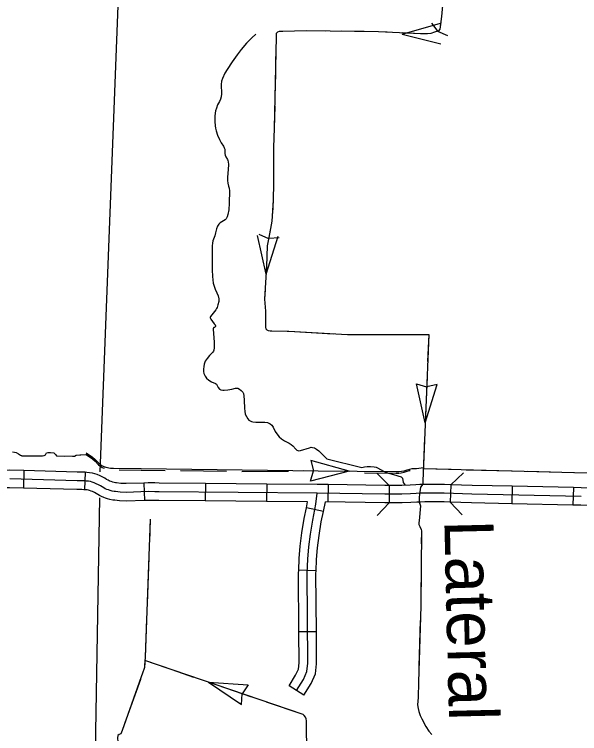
# Model space of a CAD drawing. Extents: x 1196286 to 1268366, y 2040822 to 2082115.
# Drawn here: x 1219934 to 1221760, y 2061099 to 2063420 of the extents above; entities that cross this region are included whole.
import ezdxf

# ---------------------------------------------------------------- set-up
doc = ezdxf.new("R2010")
doc.units = 0
for name, color, linetype in [('60', 7, 'Continuous'), ('61', 7, 'Continuous'), ('62', 7, 'Continuous'), ('63', 7, 'Continuous'), ('Level 83', 7, 'Continuous')]:
    doc.layers.add(name, color=color, linetype=linetype)

msp = doc.modelspace()

# ---------------------------------------------------------------- linework, layer by layer
at = {"layer": '60'}
for points in [[(1220211.7, 2061943.6), (1220286.5, 2063894.5)], [(1220209.5, 2061859.4), (1220176.2, 2059909.8)]]:
    msp.add_lwpolyline(points, dxfattribs=at)
at = {"layer": '61'}
for p, q in [((1219965.2, 2061947.6), (1219963.7, 2061891.3)), ((1220163.5, 2061942.2), (1220161.1, 2061886)), ((1220352.4, 2061907.5), (1220354.2, 2061851.3)), ((1220551.5, 2061905.9), (1220551, 2061849.7)), ((1220749.4, 2061904.4), (1220749, 2061848.2)), ((1220947.7, 2061902.6), (1220946.7, 2061846.3)), ((1221145.1, 2061899.5), (1221145.3, 2061843.3)), ((1221344, 2061902), (1221342.2, 2061845.8)), ((1221541.6, 2061897.1), (1221540.5, 2061840.9)), ((1221739.6, 2061893), (1221738.4, 2061836.7)), ((1220932.4, 2061816), (1220877.3, 2061827.3)), ((1220908.8, 2061624.2), (1220852.6, 2061626.7)), ((1220909.7, 2061427.7), (1220853.5, 2061427.3)), ((1220869.3, 2061223.5), (1220821.7, 2061253.5))]:
    msp.add_line(p, q, dxfattribs=at)
for points in [[(1219965.2, 2061947.6), (1219919.7, 2061948.8), (1219766.3, 2061948)], [(1220163.5, 2061942.2), (1220160.9, 2061942.3), (1220154.6, 2061942.6), (1220137.6, 2061942.9), (1219965.2, 2061947.6)], [(1221764.9, 2061864.3), (1221411.8, 2061871.7), (1221322.6, 2061874.6), (1221286.6, 2061874.9), (1221259.2, 2061874.8), (1221245.3, 2061874.4), (1221232.4, 2061873.7), (1221213.9, 2061872.9), (1221186.2, 2061871.7), (1221157.7, 2061871.5), (1221130.9, 2061871.3), (1220912, 2061875.1), (1220401.6, 2061879), (1220387.6, 2061879.6), (1220366.5, 2061879.8), (1220295.3, 2061877.5), (1220276.4, 2061878.2), (1220261.3, 2061879.8), (1220256.4, 2061880.2), (1220250, 2061881.6), (1220243.8, 2061883.5), (1220238.2, 2061885.4), (1220233.1, 2061887.2), (1220228, 2061889.3), (1220223.1, 2061892), (1220218, 2061894.9), (1220212.5, 2061898.1), (1220206.1, 2061901.4), (1220199, 2061905.5), (1220192, 2061908.2), (1220185.7, 2061910.4), (1220180.1, 2061912), (1220173.3, 2061913.1), (1220166.1, 2061913.9), (1220159.6, 2061914.2), (1220153.6, 2061914.5), (1220136.9, 2061914.8), (1219919.4, 2061920.7)], [(1220352.4, 2061907.5), (1220295.4, 2061905.6), (1220278.3, 2061906.3), (1220264.1, 2061907.7), (1220260.7, 2061908.1), (1220257, 2061908.9), (1220252.4, 2061910.3), (1220247.3, 2061912), (1220243.1, 2061913.4), (1220240.2, 2061914.7), (1220236.9, 2061916.5), (1220232.2, 2061919.2), (1220226, 2061922.8), (1220219.6, 2061926.1), (1220211.3, 2061930.8), (1220201.7, 2061934.7), (1220194, 2061937.2), (1220186.2, 2061939.4), (1220177.3, 2061940.9), (1220168.3, 2061942), (1220163.5, 2061942.2)], [(1220551.5, 2061905.9), (1220402.3, 2061907.1), (1220388.4, 2061907.7), (1220366.2, 2061907.9), (1220352.4, 2061907.5)], [(1220749.4, 2061904.4), (1220551.5, 2061905.9)], [(1220947.7, 2061902.6), (1220912.4, 2061903.2), (1220749.4, 2061904.4)], [(1221145.1, 2061899.5), (1221131.1, 2061899.4), (1220947.7, 2061902.6)], [(1221344, 2061902), (1221323.2, 2061902.7), (1221286.7, 2061903), (1221258.8, 2061902.9), (1221244.1, 2061902.5), (1221231, 2061901.8), (1221212.7, 2061901), (1221185.5, 2061899.8), (1221157.5, 2061899.6), (1221145.1, 2061899.5)], [(1221541.6, 2061897.1), (1221412.5, 2061899.8), (1221344, 2061902)], [(1219963.7, 2061891.3), (1219919.1, 2061892.5), (1219766.6, 2061891.7)], [(1220161.1, 2061886), (1220158.3, 2061886.1), (1220152.7, 2061886.4), (1220136.2, 2061886.7), (1219963.7, 2061891.3)], [(1220354.2, 2061851.3), (1220295.2, 2061849.4), (1220274.4, 2061850.1), (1220258.4, 2061851.8), (1220252.1, 2061852.4), (1220242.9, 2061854.3), (1220235.2, 2061856.7), (1220229.1, 2061858.7), (1220223, 2061860.9), (1220215.8, 2061863.9), (1220209.3, 2061867.5), (1220203.9, 2061870.6), (1220199, 2061873.4), (1220192.7, 2061876.6), (1220186.7, 2061880.1), (1220182.3, 2061881.8), (1220177.4, 2061883.5), (1220173.9, 2061884.5), (1220169.4, 2061885.2), (1220163.8, 2061885.9), (1220161.1, 2061886)], [(1220845.5, 2061238.5), (1220867.7, 2061273.8), (1220879.1, 2061299.3), (1220882.3, 2061325.9), (1220880.3, 2061616.7), (1220882.2, 2061662.2), (1220885, 2061701.4), (1220890.9, 2061742.5), (1220898, 2061787.7), (1220908.4, 2061839), (1220912, 2061875.1)], [(1221739.6, 2061893), (1221541.6, 2061897.1)], [(1221937.5, 2061889.1), (1221765.4, 2061892.4), (1221739.6, 2061893)], [(1220551, 2061849.7), (1220400.9, 2061850.8), (1220386.9, 2061851.4), (1220366.8, 2061851.7), (1220354.2, 2061851.3)], [(1220749, 2061848.2), (1220551, 2061849.7)], [(1220881.4, 2061847.2), (1220749, 2061848.2)], [(1220877.3, 2061827.3), (1220881.4, 2061847.2)], [(1220932.4, 2061816), (1220938.7, 2061846.5)], [(1221145.3, 2061843.3), (1221130.7, 2061843.2), (1220938.7, 2061846.5)], [(1221342.2, 2061845.8), (1221322.1, 2061846.5), (1221286.6, 2061846.7), (1221259.6, 2061846.6), (1221246.4, 2061846.3), (1221233.7, 2061845.6), (1221215.1, 2061844.8), (1221186.9, 2061843.6), (1221157.9, 2061843.3), (1221145.3, 2061843.3)], [(1221540.5, 2061840.9), (1221411, 2061843.6), (1221342.2, 2061845.8)], [(1221738.4, 2061836.7), (1221540.5, 2061840.9)], [(1221936.4, 2061832.8), (1221764.3, 2061836.2), (1221738.4, 2061836.7)], [(1220852.6, 2061626.7), (1220854.2, 2061663.7), (1220857, 2061704.3), (1220863, 2061746.7), (1220870.3, 2061792.7), (1220877.3, 2061827.3)], [(1220908.8, 2061624.2), (1220910.3, 2061660.6), (1220912.9, 2061698.4), (1220918.7, 2061738.3), (1220925.6, 2061782.7), (1220932.4, 2061816)], [(1220853.5, 2061427.3), (1220852.2, 2061617.2), (1220852.6, 2061626.7)], [(1220909.7, 2061427.7), (1220908.4, 2061616.2), (1220908.8, 2061624.2)], [(1220821.7, 2061253.5), (1220842.8, 2061287.1), (1220851.7, 2061306.9), (1220854.2, 2061327.5), (1220853.5, 2061427.3)], [(1220869.3, 2061223.5), (1220892.5, 2061260.5), (1220906.5, 2061291.7), (1220910.5, 2061324.3), (1220909.7, 2061427.7)]]:
    msp.add_lwpolyline(points, dxfattribs=at)
at = {"layer": '62'}
for points in [[(1220714.2, 2063355.6), (1220701.3, 2063344.2), (1220683.9, 2063326.8), (1220666.9, 2063306.9), (1220653.5, 2063289.3), (1220637.3, 2063266.3), (1220621.4, 2063241.7), (1220614.4, 2063229.8), (1220606.5, 2063213.4), (1220603.4, 2063204), (1220602.2, 2063193.4), (1220603.4, 2063163.5), (1220601.8, 2063153.5), (1220599.7, 2063146), (1220596.4, 2063139), (1220590.3, 2063127.7), (1220586.7, 2063117.4), (1220583.9, 2063108.2), (1220581.7, 2063092.3), (1220581.4, 2063073.7), (1220582.4, 2063060), (1220583.7, 2063052.3), (1220586, 2063043.6), (1220590.8, 2063030.6), (1220596.9, 2063016.1), (1220602.7, 2063005.5), (1220609.3, 2062995), (1220612.3, 2062989.3), (1220613.8, 2062985.4), (1220614.2, 2062980.6), (1220614.1, 2062971.1), (1220614.7, 2062965.9), (1220617.2, 2062960.4), (1220622.7, 2062951.9), (1220624, 2062948.4), (1220624.9, 2062944.3), (1220625.5, 2062935.5), (1220624.8, 2062919.3), (1220622.3, 2062894.9), (1220622.6, 2062884.3), (1220623.9, 2062875.7), (1220626.2, 2062865.5), (1220627.7, 2062859), (1220628.8, 2062850.5), (1220628.5, 2062810.8), (1220627.1, 2062789.2), (1220624, 2062773.7), (1220621.7, 2062766.8), (1220618.3, 2062760.5), (1220614.9, 2062757.4), (1220599.1, 2062747.1), (1220594.8, 2062742.8), (1220590.2, 2062736.2), (1220587.3, 2062728.1), (1220584.1, 2062714.8), (1220581.4, 2062705.3), (1220575.7, 2062689.5), (1220574.2, 2062681.3), (1220573.6, 2062672.9), (1220573.1, 2062639.6), (1220572.8, 2062595.9), (1220573.8, 2062574.3), (1220575, 2062563), (1220576.9, 2062553), (1220579.4, 2062543.2), (1220583.1, 2062533.1), (1220588.7, 2062521.7), (1220592.6, 2062511.2), (1220594.2, 2062502.3), (1220594.3, 2062493.5), (1220591.9, 2062482.3), (1220589, 2062473.6), (1220587.6, 2062470.3), (1220585.3, 2062466.9), (1220568.2, 2062445.1), (1220567.1, 2062442.7), (1220567, 2062440.2), (1220567.4, 2062438.3), (1220568.4, 2062436.8), (1220579.6, 2062421.7), (1220582.6, 2062418.4), (1220583.3, 2062417.4), (1220584, 2062416.1), (1220584.4, 2062414.8), (1220584.4, 2062413.7), (1220584.1, 2062412.5), (1220583.3, 2062411.3), (1220581.6, 2062410), (1220578.6, 2062409), (1220577.8, 2062408.2), (1220577.2, 2062407.6), (1220576.6, 2062405.9), (1220576.4, 2062404.1)], [(1220576.4, 2062404.1), (1220579.1, 2062361.7), (1220579.3, 2062343.6), (1220578.7, 2062336.8), (1220577.1, 2062332.6), (1220574.2, 2062328.6), (1220565, 2062319.1), (1220556.6, 2062309.5), (1220550.4, 2062300.4), (1220547.3, 2062291.4), (1220545.8, 2062283.8), (1220544.9, 2062275.3), (1220545.1, 2062267.9), (1220546.5, 2062261.1), (1220550.1, 2062252.4), (1220555, 2062246.1), (1220562, 2062239.4), (1220571.5, 2062234.5), (1220584.3, 2062228.9), (1220587, 2062226.8), (1220589.7, 2062222.8), (1220592.9, 2062215.9), (1220596.7, 2062210.6), (1220601.6, 2062208.3), (1220607.4, 2062207.2), (1220612.4, 2062207.1), (1220623.7, 2062208.2), (1220636.4, 2062210.6), (1220648.4, 2062213.5), (1220652.3, 2062213.8), (1220655.8, 2062213.2), (1220661.4, 2062210.7), (1220666.9, 2062206.4), (1220671.8, 2062201.1), (1220674.2, 2062196.1), (1220675.8, 2062189), (1220676.9, 2062175.3), (1220677.5, 2062147.6), (1220678.4, 2062139.3), (1220679.9, 2062129.8), (1220683.7, 2062122.2), (1220688.5, 2062114.6), (1220692, 2062110.9), (1220695.8, 2062108.3), (1220700.7, 2062106.4), (1220704.8, 2062105.1), (1220714.7, 2062104.4), (1220743.6, 2062104.5), (1220752.2, 2062102.7), (1220756.4, 2062100.9), (1220760.6, 2062099), (1220765.8, 2062093.9), (1220769.8, 2062087.8), (1220776.8, 2062074.4), (1220782.5, 2062066.2), (1220789.4, 2062056.8), (1220796.6, 2062050.2), (1220807.2, 2062043.3), (1220822.3, 2062035.8), (1220827.8, 2062032.3), (1220833.8, 2062027.4), (1220843.3, 2062016.9), (1220846.1, 2062014), (1220849.4, 2062012.5), (1220852.3, 2062012), (1220858, 2062012.4), (1220887, 2062021.4), (1220893.1, 2062022.8), (1220897.6, 2062022.6), (1220903.3, 2062021.5), (1220909.9, 2062017), (1220917.2, 2062011), (1220925.9, 2062002.7), (1220943.9, 2061986.2), (1221056.1, 2061958.1), (1221064.7, 2061960), (1221074.2, 2061960.9), (1221084.9, 2061961.1), (1221096.7, 2061960.1), (1221102.5, 2061958.5), (1221107.4, 2061956.4), (1221126.8, 2061946.3), (1221134.3, 2061942.9), (1221142.4, 2061939.9), (1221159.2, 2061934.6), (1221183.9, 2061927.9), (1221187.7, 2061923.2), (1221190.5, 2061908.9), (1221196.1, 2061900.3)]]:
    msp.add_lwpolyline(points, dxfattribs=at)
at = {"layer": '63'}
for p, q in [((1221187.2, 2063356.5), (1221311.1, 2063391.4)), ((1221281.3, 2063392), (1221302, 2063364.6)), ((1221333.8, 2063351), (1221302.3, 2063364.4)), ((1221187.2, 2063356.5), (1221311.9, 2063324.8)), ((1220724.3, 2062710.9), (1220755.3, 2062696.2)), ((1220747.4, 2062581.2), (1220719.4, 2062706.8)), ((1220747.4, 2062581.2), (1220786, 2062704)), ((1220789.9, 2062699), (1220755.7, 2062696.2)), ((1221261.2, 2062102.3), (1221232.9, 2062227.9)), ((1221232.9, 2062227.9), (1221265.6, 2062217.7)), ((1221261.2, 2062102.3), (1221299.4, 2062225.2)), ((1221299.4, 2062225.2), (1221266, 2062217.7)), ((1221015.7, 2061946.1), (1220891.6, 2061980.4)), ((1220891.6, 2061980.4), (1220900.2, 2061947.3)), ((1220891.1, 2061913.8), (1220900.2, 2061946.8)), ((1221015.7, 2061946.1), (1220891.1, 2061913.8)), ((1220561.2, 2061264.6), (1220668, 2061192.9)), ((1220561.2, 2061264.6), (1220689.6, 2061255.9)), ((1220689.6, 2061255.9), (1220670.5, 2061227.5)), ((1220668, 2061192.9), (1220670.3, 2061227.1))]:
    msp.add_line(p, q, dxfattribs=at)
for points in [[(1221323.6, 2063520.7), (1221314.1, 2063413.2), (1221308.1, 2063372.2), (1221303.7, 2063366.5), (1221291, 2063362), (1221279.5, 2063357.9), (1221269.1, 2063357.5), (1221246.5, 2063357.3), (1221110.3, 2063363.9), (1220876.8, 2063366.4), (1220801.6, 2063364.7), (1220790, 2063364.1), (1220784, 2063362.6), (1220780.2, 2063357.8), (1220779.8, 2063347.8), (1220773.6, 2063052.9), (1220770.9, 2062989.9), (1220771.7, 2062875.6), (1220770.5, 2062819.9), (1220765.8, 2062753), (1220756.1, 2062699.4), (1220751.3, 2062672.9), (1220748.5, 2062606.3), (1220744.2, 2062536.1), (1220742.7, 2062501), (1220745.9, 2062462), (1220745.2, 2062415.9), (1220745.5, 2062410.8), (1220747, 2062405.5), (1220749.4, 2062401.8), (1220753.9, 2062399.4), (1220760.3, 2062398.4), (1220820.8, 2062397.5), (1221010.7, 2062386.4), (1221272.6, 2062387.3), (1221253.6, 2061913.7), (1221253.4, 2061903.5), (1221249.9, 2061899.3), (1221246.4, 2061894.3), (1221245.2, 2061887), (1221242.7, 2061872.4), (1221241.7, 2061859.5), (1221241.3, 2061849.8), (1221241.2, 2061848), (1221243.7, 2061840.9), (1221245.7, 2061833.9), (1221241.3, 2061785.6), (1221241.1, 2061779.7), (1221240.8, 2061773.7), (1221244.2, 2061767.1), (1221248.4, 2061758.1), (1221248.7, 2061753), (1221246.6, 2061510.8), (1221239.3, 2061264.7), (1221238.1, 2061215.8), (1221237.2, 2061203.8), (1221236.6, 2061191.9), (1221238, 2061179.8), (1221240.8, 2061170), (1221244.9, 2061157.8), (1221250.4, 2061147), (1221256.3, 2061134.7), (1221262.7, 2061122.4), (1221272.7, 2061106.8), (1221282.3, 2061095.7)], [(1221311.5, 2063395.2), (1221308.1, 2063372.2), (1221303.7, 2063366.5), (1221291, 2063362), (1221279.5, 2063357.9), (1221269.1, 2063357.5), (1221246.5, 2063357.3), (1221187.3, 2063360.2)], [(1220939.9, 2063365.7), (1220876.8, 2063366.4), (1220801.6, 2063364.7), (1220791.4, 2063364.2)], [(1221063.6, 2063364.4), (1220989.4, 2063365.2)], [(1221137.8, 2063362.6), (1221110.3, 2063363.9), (1221063.6, 2063364.4)], [(1220779.2, 2063322), (1220776.2, 2063173.6)], [(1220775.1, 2063124.1), (1220773.6, 2063052.9), (1220770.9, 2062989.9), (1220771, 2062975.6)], [(1220771.3, 2062926.1), (1220771.7, 2062875.6), (1220770.5, 2062819.9), (1220767.6, 2062777.8)], [(1220761.4, 2062728.7), (1220756.1, 2062699.4), (1220751.3, 2062672.9), (1220748.5, 2062606.3), (1220747, 2062581.2)], [(1220744.1, 2062531.8), (1220742.7, 2062501), (1220745.9, 2062462), (1220745.8, 2062457.7)], [(1220745.8, 2062457.7), (1220745.2, 2062415.9), (1220745.5, 2062410.8), (1220747, 2062405.5), (1220749.4, 2062401.8), (1220753.9, 2062399.4), (1220760.3, 2062398.4), (1220766.1, 2062398.4)], [(1220815.6, 2062397.6), (1220820.8, 2062397.5), (1220963.9, 2062389.1)], [(1221013.3, 2062386.4), (1221161.8, 2062386.9)], [(1221211.3, 2062387.1), (1221272.6, 2062387.3), (1221269.1, 2062300.2)], [(1221267.1, 2062250.7), (1221261.2, 2062102.3)], [(1221259.2, 2062052.9), (1221253.6, 2061913.7), (1221253.4, 2061904.5)], [(1219928.1, 2062007.8), (1219934.7, 2062007.5), (1219940.4, 2062005.9), (1219947.4, 2062001.7), (1219954.3, 2061997.2), (1219958.7, 2061995.6), (1219963.3, 2061994.9), (1220024.7, 2061995.1), (1220030.5, 2061996.3), (1220034.4, 2061998.5), (1220038.1, 2062005.2), (1220042.3, 2062005.8), (1220051.3, 2062006), (1220062.3, 2062004.5), (1220066.9, 2061999.8), (1220070.2, 2061995.2), (1220122.3, 2061993.8), (1220128.3, 2061994.8), (1220133.4, 2061997.1), (1220165.5, 2062000.1)], [(1219957.3, 2061996.1), (1219958.7, 2061995.6), (1219963.3, 2061994.9), (1220024.7, 2061995.1), (1220030.5, 2061996.3), (1220034.4, 2061998.5), (1220038.1, 2062005.2), (1220042.3, 2062005.8), (1220051.3, 2062006), (1220062.3, 2062004.5), (1220066.9, 2061999.8), (1220070.2, 2061995.2), (1220096.6, 2061994.5)], [(1220145.4, 2061998.2), (1220165.5, 2062000.1)], [(1220165.5, 2062000.1), (1220166, 2061999.8), (1220186.4, 2061986), (1220195.1, 2061978), (1220206.5, 2061966.6), (1220211.9, 2061962.1), (1220218, 2061958), (1220224.3, 2061955.4)], [(1220165.8, 2062005.2), (1220166.2, 2062004.8), (1220186.6, 2061991.1), (1220195.3, 2061983.1), (1220206.7, 2061971.7), (1220212.1, 2061967.1), (1220218.2, 2061963.1), (1220229.9, 2061958.3), (1220244.6, 2061955.3), (1220254.1, 2061955.3), (1220344.1, 2061954.3), (1220915.4, 2061946.9), (1221166.9, 2061944.9), (1221175.8, 2061945), (1221184.1, 2061945.6), (1221193.3, 2061947.4), (1221202.8, 2061950.5), (1221211.1, 2061952.8), (1221219.4, 2061954.1), (1221226.9, 2061954.2), (1221233.1, 2061954), (1221255.4, 2061957.8)], [(1220273, 2061950.1), (1220343.9, 2061949.3), (1220421.5, 2061948.3)], [(1220471, 2061947.6), (1220619.5, 2061945.7)], [(1220669, 2061945), (1220819.8, 2061945.9)], [(1220867.2, 2061947.5), (1220915.4, 2061946.9), (1221015.7, 2061946.1)], [(1221064.9, 2061940.7), (1221166.7, 2061939.9), (1221175.6, 2061939.9), (1221183.8, 2061940.5), (1221193, 2061942.4), (1221202.5, 2061945.4), (1221210.9, 2061947.8), (1221212.4, 2061948)], [(1223298.1, 2061910.4), (1222846.3, 2061918.1), (1222831.8, 2061920.1), (1222647.1, 2061920.8), (1222314.4, 2061925.1), (1221255.1, 2061953.2)], [(1221344.5, 2061950.8), (1221255.1, 2061953.2)], [(1221542.5, 2061945.6), (1221394, 2061949.5)], [(1221740.4, 2061940.3), (1221591.9, 2061944.3)], [(1221242.2, 2061846.1), (1221245.7, 2061833.9), (1221241.3, 2061785.6), (1221241.3, 2061784.3)], [(1220373.4, 2061791.1), (1220356.9, 2061345.9), (1220355.6, 2061331.6), (1220355.1, 2061319.9), (1220354.5, 2061312.1), (1220352.6, 2061306.1), (1220349.6, 2061297.4), (1220282.3, 2061108.8), (1220278.6, 2061097.9), (1220273.2, 2061095.7), (1220268, 2061092.5), (1220267, 2061085.4), (1220269.1, 2061059.3), (1220281.1, 2060860.8), (1220313.8, 2060712.2), (1220437.3, 2060130), (1220423.2, 2060105.8), (1220285.2, 2059654.1)], [(1220373.4, 2061791.1), (1220370.6, 2061716.9)], [(1221241.3, 2061784.3), (1221241.1, 2061779.7), (1221240.8, 2061773.7), (1221244.2, 2061767.1), (1221248.4, 2061758.1), (1221248.7, 2061753), (1221248.3, 2061711.9)], [(1220368.8, 2061667.4), (1220363.3, 2061519)], [(1221247.9, 2061662.4), (1221246.6, 2061513.9)], [(1220361.5, 2061469.6), (1220356.9, 2061345.9), (1220355.6, 2061331.6), (1220355.2, 2061321.2)], [(1221245.2, 2061464.4), (1221240.8, 2061316)], [(1221106.7, 2060641.8), (1220884, 2060645.6), (1220877.8, 2061125), (1220877.5, 2061140.1), (1220876.8, 2061147.1), (1220874.8, 2061152.2), (1220870.8, 2061157), (1220866.9, 2061160.2), (1220355.9, 2061334.7)], [(1220444, 2061304.6), (1220373.8, 2061328.6)], [(1220514.3, 2061280.6), (1220444, 2061304.6)], [(1220341.3, 2061274), (1220291.3, 2061134.1)], [(1220701.7, 2061216.6), (1220561.2, 2061264.6)], [(1221239.4, 2061266.5), (1221239.3, 2061264.7), (1221238.1, 2061215.8), (1221237.2, 2061203.8), (1221236.6, 2061191.9), (1221238, 2061179.8), (1221240.8, 2061170), (1221244.9, 2061157.8), (1221250.4, 2061147), (1221256.3, 2061134.7), (1221262.3, 2061123.3)], [(1220877.4, 2061140.5), (1220876.8, 2061147.1), (1220874.8, 2061152.2), (1220870.8, 2061157), (1220866.9, 2061160.2), (1220748.5, 2061200.6)]]:
    msp.add_lwpolyline(points, dxfattribs=at)
at = {"layer": 'Level 83'}
for points in [[(1221105.2, 2061939.1), (1221145.1, 2061899.5)], [(1221344, 2061902), (1221385.1, 2061940.5)], [(1221145.3, 2061843.3), (1221105.7, 2061803.3)], [(1221380.7, 2061804.8), (1221342.2, 2061845.8)]]:
    msp.add_lwpolyline(points, dxfattribs=at)

# ---------------------------------------------------------------- texts
at = {"layer": '63'}
msp.add_text('Lateral', height=158.4, rotation=271.3735, dxfattribs=at).set_placement((1221322.9, 2061786.9))

doc.saveas('drawing.dxf')
